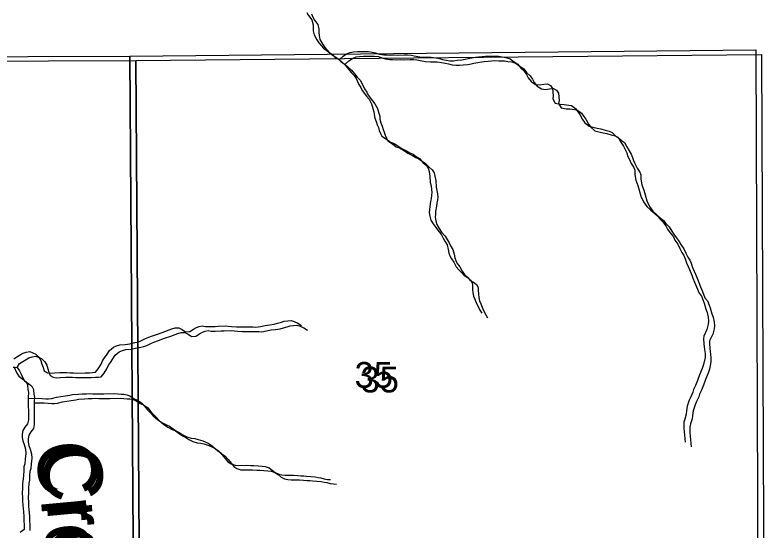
# Model space of a CAD drawing. Extents: x -21.1 to 50.3, y 0 to 22.1.
# Drawn here: x 48.021 to 49.237, y 19.975 to 20.81 of the extents above; entities that cross this region are included whole.
import ezdxf

# ---------------------------------------------------------------- set-up
doc = ezdxf.new("R2010")
doc.units = 0
for name, color, linetype in [('GM_X_Minor_River', 7, 'Continuous'), ('GM_X_Minor_River_Text', 7, 'Continuous'), ('GM_X_Section', 7, 'Continuous'), ('GM_X_Section_Text', 7, 'Continuous')]:
    doc.layers.add(name, color=color, linetype=linetype)

msp = doc.modelspace()

# ---------------------------------------------------------------- linework, layer by layer
at = {"layer": 'GM_X_Minor_River'}
for points in [[(48.4948, 20.8141), (48.4974, 20.8092), (48.5028, 20.8024), (48.5048, 20.7944), (48.5048, 20.7895), (48.5052, 20.7845), (48.5064, 20.7777), (48.511, 20.7698), (48.5141, 20.7648), (48.5217, 20.7565), (48.5263, 20.7531), (48.532, 20.749), (48.5366, 20.746), (48.5408, 20.7414), (48.5469, 20.7377), (48.5523, 20.7331), (48.5573, 20.7282), (48.5623, 20.7222), (48.5665, 20.7169), (48.5715, 20.712), (48.5745, 20.707), (48.5788, 20.6976), (48.5822, 20.6927), (48.5845, 20.6877), (48.5914, 20.6783), (48.5957, 20.6737), (48.5995, 20.6658), (48.6018, 20.6582), (48.6034, 20.6533), (48.6038, 20.6487), (48.6053, 20.6426), (48.6073, 20.6373), (48.6088, 20.632), (48.6108, 20.6275), (48.6119, 20.6229), (48.6142, 20.618), (48.6165, 20.6134), (48.6242, 20.6085), (48.6303, 20.604), (48.6353, 20.6022), (48.6406, 20.5991), (48.649, 20.5935), (48.6566, 20.5897), (48.662, 20.5863), (48.667, 20.5841), (48.6723, 20.5807), (48.6773, 20.5773), (48.6834, 20.5705)], [(48.5021, 20.8123), (48.5044, 20.8066), (48.5071, 20.8017), (48.5124, 20.7949), (48.5144, 20.7869), (48.5144, 20.782), (48.5148, 20.777), (48.516, 20.7702), (48.5206, 20.7623), (48.5237, 20.7573), (48.5314, 20.749), (48.5359, 20.7456), (48.5417, 20.7415), (48.5463, 20.7385), (48.5505, 20.7339), (48.5566, 20.7302), (48.5619, 20.7256), (48.5669, 20.7207), (48.5719, 20.7147), (48.5761, 20.7094), (48.5811, 20.7045), (48.5842, 20.6995), (48.5884, 20.6901), (48.5919, 20.6852), (48.5942, 20.6802), (48.6011, 20.6708), (48.6053, 20.6662), (48.6091, 20.6583), (48.6115, 20.6507), (48.613, 20.6458), (48.6134, 20.6412), (48.615, 20.6351), (48.6169, 20.6298), (48.6185, 20.6245), (48.6204, 20.62), (48.6216, 20.6154), (48.6239, 20.6105), (48.6262, 20.6059), (48.6338, 20.601), (48.6399, 20.5965), (48.6449, 20.5947), (48.6502, 20.5916), (48.6586, 20.586), (48.6663, 20.5822), (48.6716, 20.5788), (48.6766, 20.5766), (48.6819, 20.5732), (48.6869, 20.5698), (48.693, 20.563)], [(48.5466, 20.7379), (48.5481, 20.7384), (48.5534, 20.7434), (48.5591, 20.7469), (48.5652, 20.7495), (48.5705, 20.7503), (48.5769, 20.7507), (48.5945, 20.7508), (48.6006, 20.7501), (48.6059, 20.7486), (48.6124, 20.7464), (48.6196, 20.7453), (48.6242, 20.7453), (48.6307, 20.745), (48.6364, 20.7454), (48.6425, 20.745), (48.6527, 20.7455), (48.6581, 20.7455), (48.6638, 20.7448), (48.6687, 20.744), (48.6779, 20.7422), (48.6859, 20.7415), (48.6904, 20.7419), (48.6965, 20.7419), (48.7038, 20.7408), (48.7099, 20.7393), (48.7148, 20.7382), (48.7209, 20.7367), (48.727, 20.736), (48.7327, 20.736), (48.7388, 20.7368), (48.746, 20.7376), (48.7517, 20.7384), (48.7563, 20.7396), (48.7624, 20.7408), (48.7685, 20.7416), (48.773, 20.742), (48.7791, 20.7427), (48.7848, 20.7432), (48.7898, 20.7436), (48.7966, 20.7432), (48.8058, 20.7433), (48.8115, 20.7422), (48.8176, 20.7414), (48.8248, 20.7392), (48.8309, 20.7339), (48.8371, 20.7302), (48.8417, 20.7241), (48.8474, 20.7192), (48.8512, 20.7135), (48.8539, 20.7082), (48.8589, 20.7022), (48.8658, 20.6976), (48.8723, 20.6969), (48.8791, 20.6981), (48.8852, 20.6985), (48.8902, 20.6959), (48.8936, 20.691), (48.8944, 20.6788), (48.8937, 20.6739), (48.8979, 20.667), (48.9059, 20.6656), (48.912, 20.6652), (48.9196, 20.6641), (48.9242, 20.6634), (48.9307, 20.6585), (48.9346, 20.6532), (48.9376, 20.6487), (48.9422, 20.6407), (48.9457, 20.6354), (48.9526, 20.6297), (48.9587, 20.6279), (48.9659, 20.6264), (48.972, 20.6253), (48.9789, 20.6234), (48.9854, 20.6216), (48.9899, 20.6193), (48.9957, 20.614), (49.0006, 20.6106), (49.0041, 20.6038), (49.0083, 20.5974), (49.0114, 20.5917), (49.0137, 20.5864), (49.0149, 20.5818), (49.0176, 20.5769), (49.021, 20.5693), (49.0253, 20.5629), (49.0268, 20.5584), (49.0272, 20.5511), (49.0288, 20.542), (49.0319, 20.5337), (49.0339, 20.5257), (49.0366, 20.5162), (49.0412, 20.5071), (49.0466, 20.4996), (49.0531, 20.4935), (49.0592, 20.4879), (49.0638, 20.4841), (49.0676, 20.4796), (49.073, 20.4739), (49.0776, 20.4671)], [(48.5563, 20.7304), (48.5577, 20.7309), (48.563, 20.7359), (48.5687, 20.7393), (48.5748, 20.742), (48.5801, 20.7428), (48.5866, 20.7432), (48.6041, 20.7433), (48.6102, 20.7426), (48.6155, 20.7411), (48.622, 20.7389), (48.6293, 20.7378), (48.6338, 20.7378), (48.6403, 20.7375), (48.646, 20.7379), (48.6521, 20.7375), (48.6624, 20.738), (48.6677, 20.738), (48.6734, 20.7373), (48.6784, 20.7365), (48.6875, 20.7347), (48.6955, 20.734), (48.7001, 20.7344), (48.7062, 20.7344), (48.7134, 20.7333), (48.7195, 20.7318), (48.7245, 20.7307), (48.7306, 20.7292), (48.7367, 20.7285), (48.7424, 20.7285), (48.7484, 20.7293), (48.7557, 20.7301), (48.7614, 20.7309), (48.7659, 20.7321), (48.772, 20.7333), (48.7781, 20.7341), (48.7827, 20.7345), (48.7888, 20.7352), (48.7945, 20.7357), (48.7994, 20.7361), (48.8063, 20.7357), (48.8154, 20.7358), (48.8211, 20.7347), (48.8272, 20.7339), (48.8345, 20.7317), (48.8406, 20.7264), (48.8467, 20.7227), (48.8513, 20.7166), (48.857, 20.7117), (48.8609, 20.706), (48.8636, 20.7007), (48.8685, 20.6947), (48.8754, 20.6901), (48.8819, 20.6894), (48.8887, 20.6906), (48.8948, 20.691), (48.8998, 20.6884), (48.9032, 20.6835), (48.9041, 20.6713), (48.9033, 20.6664), (48.9076, 20.6595), (48.9156, 20.6581), (48.9217, 20.6577), (48.9293, 20.6566), (48.9339, 20.6559), (48.9404, 20.651), (48.9442, 20.6457), (48.9473, 20.6412), (48.9519, 20.6332), (48.9553, 20.6279), (48.9622, 20.6222), (48.9683, 20.6204), (48.9756, 20.6189), (48.9816, 20.6178), (48.9885, 20.6159), (48.995, 20.6141), (48.9996, 20.6118), (49.0053, 20.6065), (49.0103, 20.6031), (49.0137, 20.5963), (49.018, 20.5899), (49.021, 20.5842), (49.0234, 20.5789), (49.0245, 20.5743), (49.0272, 20.5694), (49.0307, 20.5618), (49.0349, 20.5554), (49.0365, 20.5508), (49.0369, 20.5436), (49.0385, 20.5345), (49.0415, 20.5262), (49.0435, 20.5182), (49.0462, 20.5087), (49.0508, 20.4996), (49.0562, 20.4921), (49.0627, 20.486), (49.0688, 20.4804), (49.0734, 20.4766), (49.0772, 20.4721), (49.0826, 20.4664), (49.0872, 20.4596)], [(48.6834, 20.5705), (48.6884, 20.5667), (48.6914, 20.5614), (48.693, 20.5561), (48.6942, 20.5489), (48.695, 20.5383), (48.6962, 20.533), (48.697, 20.5273), (48.6974, 20.5223), (48.697, 20.5178), (48.6963, 20.5121), (48.6955, 20.5075), (48.6941, 20.4991), (48.6937, 20.4946), (48.6934, 20.4896), (48.6942, 20.484), (48.6961, 20.4775), (48.6996, 20.4711), (48.7038, 20.4654), (48.7095, 20.4586), (48.713, 20.4533), (48.7161, 20.448), (48.7184, 20.4431), (48.7222, 20.437), (48.7241, 20.4298), (48.7253, 20.4237), (48.7269, 20.4192), (48.7292, 20.4146), (48.733, 20.4089), (48.7372, 20.4018), (48.7411, 20.3968), (48.7461, 20.3919), (48.7503, 20.387), (48.7552, 20.3844), (48.7602, 20.3802), (48.7629, 20.3757), (48.7633, 20.3711), (48.7633, 20.3647), (48.7641, 20.3594), (48.7653, 20.354), (48.7672, 20.3491), (48.7695, 20.3434), (48.7719, 20.3381), (48.7753, 20.3313), (48.7784, 20.3264)], [(48.693, 20.563), (48.698, 20.5592), (48.7011, 20.5539), (48.7026, 20.5486), (48.7038, 20.5414), (48.7046, 20.5308), (48.7058, 20.5255), (48.7066, 20.5198), (48.707, 20.5148), (48.7067, 20.5103), (48.7059, 20.5046), (48.7052, 20.5), (48.7037, 20.4916), (48.7034, 20.4871), (48.703, 20.4821), (48.7038, 20.4764), (48.7057, 20.47), (48.7092, 20.4636), (48.7134, 20.4579), (48.7192, 20.4511), (48.7226, 20.4458), (48.7257, 20.4405), (48.728, 20.4356), (48.7318, 20.4295), (48.7338, 20.4223), (48.735, 20.4162), (48.7365, 20.4117), (48.7388, 20.4071), (48.7427, 20.4014), (48.7469, 20.3943), (48.7507, 20.3893), (48.7557, 20.3844), (48.7599, 20.3795), (48.7649, 20.3769), (48.7698, 20.3727), (48.7725, 20.3682), (48.7729, 20.3636), (48.773, 20.3572), (48.7738, 20.3518), (48.7749, 20.3465), (48.7769, 20.3416), (48.7792, 20.3359), (48.7815, 20.3306), (48.785, 20.3238), (48.788, 20.3189)], [(49.0776, 20.4671), (49.0799, 20.4625), (49.0845, 20.4569), (49.0895, 20.45), (49.0918, 20.4451), (49.0968, 20.4383), (49.1002, 20.4315), (49.1033, 20.4247), (49.1064, 20.4197), (49.1087, 20.4148), (49.111, 20.408), (49.1133, 20.4019), (49.1156, 20.397), (49.1195, 20.3879), (49.1211, 20.3834), (49.1238, 20.3765), (49.1268, 20.3693), (49.1311, 20.3587), (49.1349, 20.3538), (49.138, 20.347), (49.1396, 20.3424), (49.1423, 20.3329), (49.1442, 20.3276), (49.1458, 20.3197), (49.1466, 20.3132), (49.1458, 20.3083), (49.144, 20.2999), (49.1387, 20.2892), (49.1384, 20.2847), (49.1388, 20.2767), (49.1396, 20.2718), (49.14, 20.2672), (49.1408, 20.2608), (49.1408, 20.2547), (49.1386, 20.2433), (49.1363, 20.2368), (49.1318, 20.2261), (49.1284, 20.217), (49.1254, 20.209), (49.1221, 20.2025), (49.1209, 20.198), (49.1176, 20.1907), (49.1149, 20.1854), (49.1119, 20.1755), (49.1108, 20.1679), (49.1101, 20.1626), (49.1079, 20.1542), (49.1067, 20.1496), (49.1064, 20.1405), (49.1072, 20.1337), (49.1076, 20.1291), (49.108, 20.1227), (49.1088, 20.117)], [(49.0872, 20.4596), (49.0895, 20.455), (49.0941, 20.4494), (49.0991, 20.4425), (49.1014, 20.4376), (49.1064, 20.4308), (49.1099, 20.424), (49.113, 20.4172), (49.116, 20.4122), (49.1183, 20.4073), (49.1207, 20.4005), (49.123, 20.3944), (49.1253, 20.3895), (49.1291, 20.3804), (49.1307, 20.3759), (49.1334, 20.369), (49.1365, 20.3618), (49.1407, 20.3512), (49.1446, 20.3463), (49.1476, 20.3395), (49.1492, 20.3349), (49.1519, 20.3254), (49.1538, 20.3201), (49.1554, 20.3122), (49.1562, 20.3057), (49.1555, 20.3008), (49.1536, 20.2924), (49.1483, 20.2817), (49.148, 20.2772), (49.1484, 20.2692), (49.1492, 20.2643), (49.1496, 20.2597), (49.1504, 20.2533), (49.1504, 20.2472), (49.1482, 20.2358), (49.146, 20.2293), (49.1415, 20.2186), (49.1381, 20.2095), (49.1351, 20.2015), (49.1317, 20.195), (49.1306, 20.1905), (49.1272, 20.1832), (49.1246, 20.1779), (49.1216, 20.168), (49.1205, 20.1604), (49.1197, 20.1551), (49.1175, 20.1467), (49.1164, 20.1421), (49.1161, 20.133), (49.1169, 20.1262), (49.1173, 20.1216), (49.1177, 20.1152), (49.1185, 20.1095)], [(48.019, 20.2523), (48.0239, 20.2553), (48.0296, 20.2588), (48.0342, 20.2615), (48.0395, 20.263), (48.0452, 20.2642), (48.0502, 20.262), (48.0548, 20.2601), (48.0597, 20.2552), (48.0632, 20.2495), (48.0647, 20.2438), (48.0667, 20.2381), (48.0686, 20.2328), (48.0736, 20.2298), (48.0782, 20.2291), (48.085, 20.2295), (48.0941, 20.2303), (48.0987, 20.2303), (48.1048, 20.23), (48.1105, 20.2296), (48.1158, 20.2296), (48.1208, 20.2293), (48.1352, 20.2294), (48.1421, 20.2298), (48.147, 20.2302), (48.1516, 20.2306), (48.1561, 20.2363), (48.1607, 20.2436), (48.1633, 20.2493), (48.1663, 20.2539), (48.1705, 20.26), (48.1743, 20.2657), (48.1807, 20.271), (48.1856, 20.2733), (48.1913, 20.2749), (48.2001, 20.2757), (48.2073, 20.2769), (48.2157, 20.2788), (48.2206, 20.2796), (48.2255, 20.2815), (48.2328, 20.2854), (48.2385, 20.2873), (48.2445, 20.2896), (48.254, 20.2931), (48.2643, 20.2966), (48.2711, 20.2993), (48.2757, 20.3008), (48.281, 20.3024), (48.2871, 20.3028), (48.2924, 20.2998), (48.2978, 20.296), (48.3046, 20.2968), (48.3107, 20.3002), (48.3156, 20.3029), (48.3202, 20.3049), (48.3248, 20.3056), (48.3301, 20.3049), (48.3366, 20.3046), (48.3461, 20.305), (48.3507, 20.3054), (48.3621, 20.3058), (48.367, 20.3055), (48.3727, 20.3048), (48.3807, 20.304), (48.4074, 20.3042), (48.4119, 20.3038), (48.4196, 20.305), (48.4272, 20.3066), (48.4344, 20.3074), (48.4416, 20.3086), (48.4469, 20.3101), (48.4534, 20.3117), (48.458, 20.3132), (48.4637, 20.314), (48.469, 20.3144), (48.4743, 20.3129), (48.4801, 20.3103), (48.4862, 20.3065)], [(48.0245, 20.2383), (48.0287, 20.2448), (48.0336, 20.2478), (48.0393, 20.2513), (48.0438, 20.254), (48.0492, 20.2555), (48.0549, 20.2567), (48.0598, 20.2545), (48.0644, 20.2526), (48.0694, 20.2477), (48.0728, 20.242), (48.0744, 20.2363), (48.0763, 20.2306), (48.0782, 20.2253), (48.0832, 20.2223), (48.0878, 20.2216), (48.0946, 20.222), (48.1038, 20.2228), (48.1083, 20.2228), (48.1144, 20.2225), (48.1201, 20.2221), (48.1255, 20.2221), (48.1304, 20.2218), (48.1449, 20.2219), (48.1517, 20.2223), (48.1567, 20.2227), (48.1612, 20.2231), (48.1658, 20.2288), (48.1703, 20.2361), (48.1729, 20.2418), (48.176, 20.2464), (48.1801, 20.2525), (48.1839, 20.2582), (48.1903, 20.2635), (48.1953, 20.2658), (48.201, 20.2674), (48.2097, 20.2682), (48.2169, 20.2694), (48.2253, 20.2713), (48.2302, 20.2721), (48.2352, 20.274), (48.2424, 20.2779), (48.2481, 20.2798), (48.2542, 20.2821), (48.2637, 20.2856), (48.2739, 20.2891), (48.2808, 20.2918), (48.2853, 20.2933), (48.2906, 20.2949), (48.2967, 20.2953), (48.3021, 20.2923), (48.3074, 20.2885), (48.3143, 20.2893), (48.3204, 20.2927), (48.3253, 20.2954), (48.3298, 20.2974), (48.3344, 20.2981), (48.3397, 20.2974), (48.3462, 20.2971), (48.3557, 20.2975), (48.3603, 20.2979), (48.3717, 20.2983), (48.3767, 20.298), (48.3824, 20.2973), (48.3904, 20.2965), (48.417, 20.2967), (48.4216, 20.2963), (48.4292, 20.2975), (48.4368, 20.2991), (48.444, 20.2999), (48.4513, 20.3011), (48.4566, 20.3026), (48.463, 20.3042), (48.4676, 20.3057), (48.4733, 20.3065), (48.4786, 20.3069), (48.484, 20.3054), (48.4897, 20.3028), (48.4958, 20.299)], [(48.0184, 20.239), (48.0245, 20.2383), (48.0287, 20.2326), (48.031, 20.2277), (48.0337, 20.2216), (48.0368, 20.2167), (48.0437, 20.2118), (48.0487, 20.2077), (48.051, 20.2027), (48.0518, 20.1951), (48.0526, 20.1902), (48.0522, 20.1826), (48.0524, 20.1458), (48.0509, 20.1393), (48.0468, 20.134), (48.0438, 20.1286), (48.0423, 20.1225), (48.0423, 20.1172), (48.0435, 20.1119), (48.0458, 20.1058), (48.0477, 20.0982), (48.0485, 20.0914), (48.0475, 20.0819), (48.0467, 20.0743), (48.0452, 20.0694)], [(48.0191, 20.2401), (48.0214, 20.2352), (48.0241, 20.2291), (48.0272, 20.2242), (48.034, 20.2193), (48.039, 20.2152), (48.0413, 20.2102), (48.0421, 20.2026), (48.0429, 20.1977), (48.0426, 20.1901), (48.0428, 20.1533), (48.0413, 20.1468), (48.0371, 20.1415), (48.0341, 20.1361), (48.0326, 20.13), (48.0327, 20.1247), (48.0338, 20.1194), (48.0362, 20.1133), (48.0381, 20.1057), (48.0389, 20.0989), (48.0378, 20.0894), (48.0371, 20.0818), (48.0356, 20.0769)], [(48.0426, 20.1882), (48.0586, 20.1883), (48.0651, 20.188), (48.0711, 20.1876), (48.0757, 20.1876), (48.0803, 20.188), (48.0886, 20.19), (48.1023, 20.1923), (48.1099, 20.1935), (48.1145, 20.1943), (48.1244, 20.1951), (48.1301, 20.1955), (48.137, 20.1956), (48.1419, 20.196), (48.1476, 20.1956), (48.1522, 20.1953), (48.1594, 20.1953), (48.1655, 20.1957), (48.1826, 20.1958), (48.1883, 20.1955), (48.1933, 20.1951), (48.1979, 20.1948), (48.2024, 20.1937), (48.2074, 20.1922), (48.2147, 20.1876), (48.22, 20.1854), (48.2269, 20.1805), (48.2311, 20.1756), (48.2361, 20.1695), (48.241, 20.1646), (48.2456, 20.1597), (48.2525, 20.154), (48.2594, 20.1491), (48.2667, 20.145), (48.272, 20.1428), (48.2777, 20.1386), (48.2831, 20.1348), (48.2884, 20.1322), (48.2934, 20.1292), (48.2999, 20.1258), (48.3071, 20.1236), (48.3128, 20.1228), (48.3182, 20.1217), (48.3258, 20.1191), (48.3346, 20.1154), (48.3418, 20.1108), (48.3468, 20.1056), (48.3518, 20.1022), (48.3571, 20.0965), (48.3621, 20.0908), (48.3667, 20.0852), (48.3717, 20.0818), (48.3782, 20.0799), (48.3839, 20.0795), (48.3968, 20.0796), (48.4037, 20.0793), (48.4086, 20.0793), (48.4155, 20.0786), (48.422, 20.0782), (48.4273, 20.0775), (48.4334, 20.0756), (48.4384, 20.0719), (48.4433, 20.0677), (48.4491, 20.0651), (48.454, 20.064), (48.4593, 20.0636), (48.4662, 20.0633), (48.4731, 20.0633), (48.4799, 20.063), (48.4849, 20.0626), (48.4898, 20.0623), (48.4944, 20.0619), (48.5012, 20.0612), (48.5081, 20.0609), (48.513, 20.0597), (48.5176, 20.059), (48.523, 20.0575), (48.5283, 20.0568), (48.5332, 20.0564)], [(48.0522, 20.1807), (48.0682, 20.1808), (48.0747, 20.1805), (48.0808, 20.1801), (48.0854, 20.1801), (48.0899, 20.1805), (48.0983, 20.1825), (48.112, 20.1848), (48.1196, 20.186), (48.1241, 20.1868), (48.134, 20.1876), (48.1397, 20.188), (48.1466, 20.1881), (48.1515, 20.1885), (48.1573, 20.1881), (48.1618, 20.1878), (48.1691, 20.1878), (48.1751, 20.1882), (48.1923, 20.1883), (48.198, 20.188), (48.2029, 20.1876), (48.2075, 20.1873), (48.2121, 20.1862), (48.217, 20.1847), (48.2243, 20.1801), (48.2296, 20.1779), (48.2365, 20.173), (48.2407, 20.1681), (48.2457, 20.162), (48.2507, 20.1571), (48.2553, 20.1522), (48.2622, 20.1465), (48.269, 20.1416), (48.2763, 20.1375), (48.2816, 20.1353), (48.2874, 20.1311), (48.2927, 20.1273), (48.2981, 20.1247), (48.303, 20.1217), (48.3095, 20.1183), (48.3168, 20.1161), (48.3225, 20.1153), (48.3278, 20.1142), (48.3354, 20.1116), (48.3442, 20.1079), (48.3515, 20.1033), (48.3565, 20.0981), (48.3614, 20.0947), (48.3668, 20.089), (48.3718, 20.0833), (48.3764, 20.0777), (48.3813, 20.0743), (48.3878, 20.0724), (48.3935, 20.072), (48.4065, 20.0721), (48.4133, 20.0718), (48.4183, 20.0718), (48.4251, 20.0711), (48.4316, 20.0707), (48.4369, 20.07), (48.443, 20.0681), (48.448, 20.0644), (48.453, 20.0602), (48.4587, 20.0576), (48.4637, 20.0565), (48.469, 20.0561), (48.4758, 20.0558), (48.4827, 20.0558), (48.4895, 20.0555), (48.4945, 20.0551), (48.4994, 20.0548), (48.504, 20.0544), (48.5109, 20.0537), (48.5177, 20.0534), (48.5227, 20.0522), (48.5273, 20.0515), (48.5326, 20.05), (48.5379, 20.0493), (48.5429, 20.0489)], [(48.0356, 20.0769), (48.0353, 20.0712), (48.0349, 20.0632), (48.0342, 20.0575), (48.0335, 20.0503), (48.0331, 20.0419), (48.0328, 20.0347), (48.0332, 20.0267), (48.0332, 20.0214), (48.034, 20.0149), (48.0349, 20.0043), (48.0353, 19.9967), (48.0357, 19.991), (48.0358, 19.9811), (48.0362, 19.9754), (48.0293, 19.9705)], [(48.0452, 20.0694), (48.0449, 20.0637), (48.0446, 20.0557), (48.0438, 20.05), (48.0431, 20.0428), (48.0428, 20.0344), (48.0424, 20.0272), (48.0429, 20.0192), (48.0429, 20.0139), (48.0437, 20.0074), (48.0445, 19.9968), (48.0449, 19.9892), (48.0453, 19.9835), (48.0454, 19.9736)]]:
    msp.add_lwpolyline(points, dxfattribs=at)
at = {"layer": 'GM_X_Section'}
for points in [[(48.2077, 20.7436), (49.2231, 20.7535), (49.2269, 19.7377), (49.1583, 19.7367), (48.2146, 19.7248)], [(47.2135, 20.7399), (48.2077, 20.7436), (48.2146, 19.7248), (48.1627, 19.7232), (47.2087, 19.7187)], [(47.2232, 20.7324), (48.2174, 20.7361), (48.2243, 19.7173), (48.1723, 19.7157), (47.2183, 19.7112)], [(48.2174, 20.7361), (49.2327, 20.746), (49.2366, 19.7302), (49.168, 19.7292), (48.2243, 19.7173)]]:
    msp.add_lwpolyline(points, close=True, dxfattribs=at)

# ---------------------------------------------------------------- texts
at = {"layer": 'GM_X_Minor_River_Text'}
for p in [(48.0544, 20.1157), (48.0641, 20.1082)]:
    msp.add_text('Creek', height=0.09473, rotation=275.3166, dxfattribs=at).set_placement(p)
at = {"layer": 'GM_X_Section_Text'}
for p in [(48.5722, 20.2053), (48.5818, 20.1978)]:
    msp.add_text('35', height=0.04186, rotation=0, dxfattribs=at).set_placement(p)

doc.saveas('drawing.dxf')
